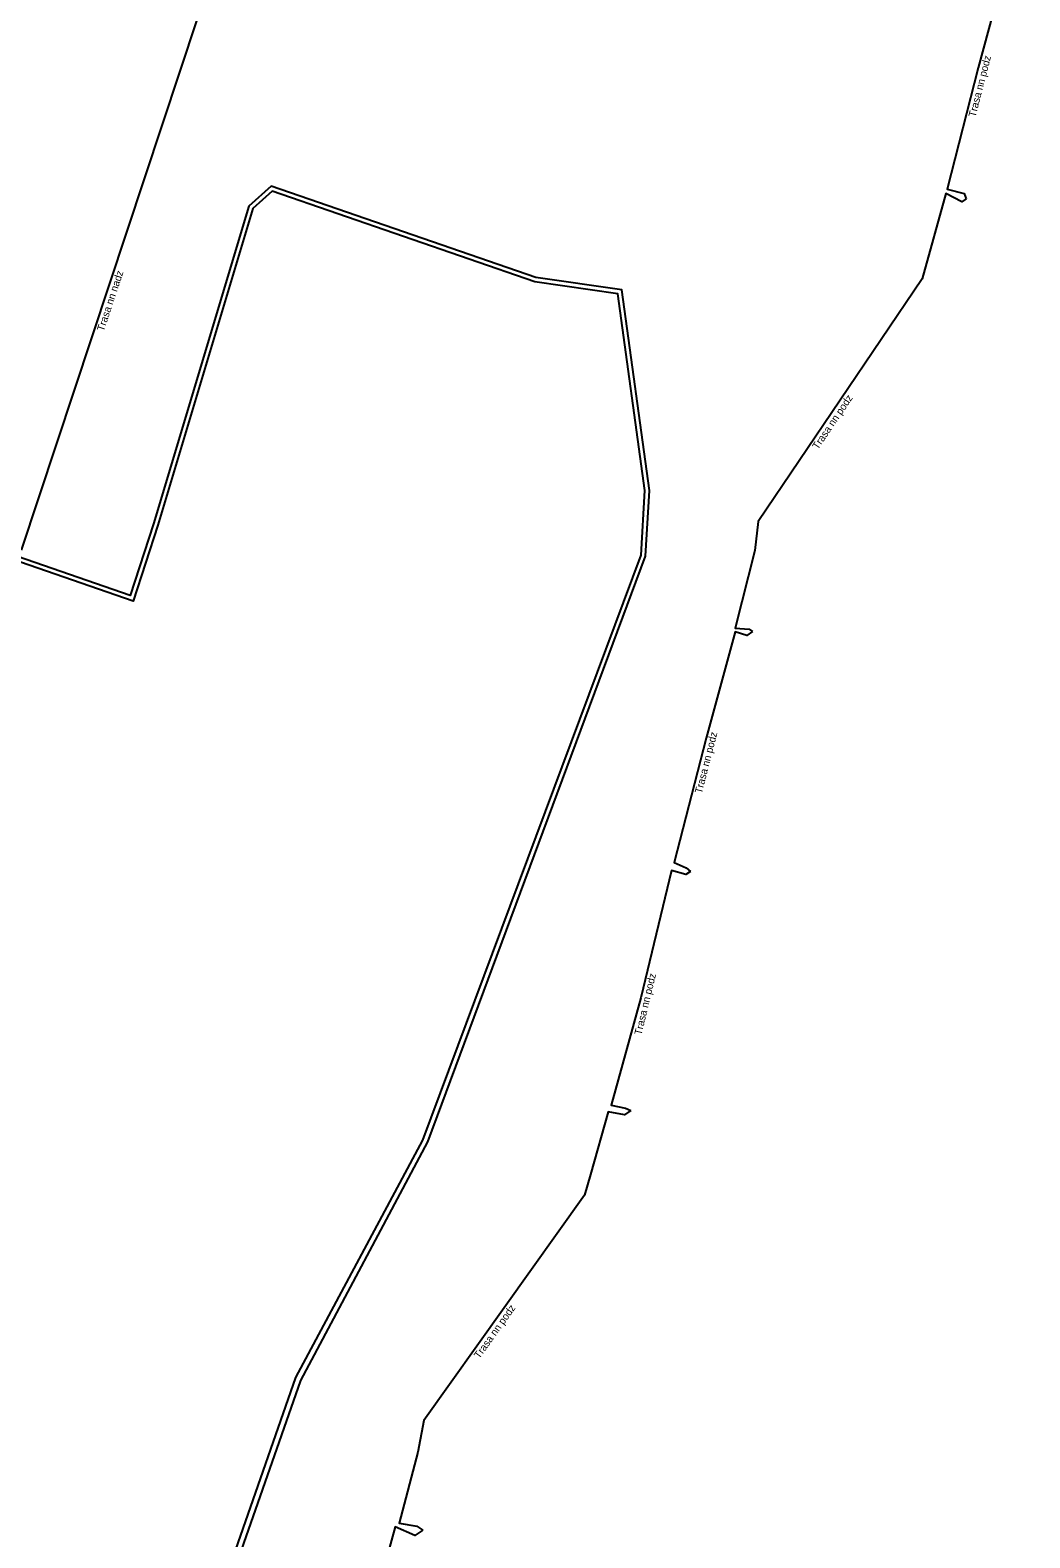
# Model space of a CAD drawing. Extents: x -843786 to -842968, y -1003095 to -1002172.
# Drawn here: x -843451.5 to -843383.8, y -1002899.3 to -1002797.2 of the extents above; entities that cross this region are included whole.
import ezdxf

# ---------------------------------------------------------------- set-up
doc = ezdxf.new("R2010")
doc.units = 0
doc.layers.add('Spojnice NN', color=7, linetype='Continuous')
doc.layers.add('Vrstva 20', color=7, linetype='Continuous')

msp = doc.modelspace()

# ---------------------------------------------------------------- linework, layer by layer
at = {"layer": 'Spojnice NN'}
for points in [[(-843383.77, -1002792.02), (-843384.13, -1002792.1), (-843385.1, -1002791.73), (-843387.26, -1002799.75), (-843389.37, -1002807.96), (-843388.22, -1002808.25), (-843388.08, -1002808.61)], [(-843452.08, -1002832.43), (-843440.16, -1002796.43)], [(-843458.03, -1002952.19), (-843448.76, -1002933.29), (-843433.14, -1002888.67), (-843424.54, -1002872.49), (-843409.8, -1002832.82), (-843409.54, -1002828.37), (-843411.41, -1002814.78), (-843417.24, -1002813.94), (-843435.17, -1002807.76), (-843436.68, -1002809.11), (-843443.13, -1002830.64), (-843444.71, -1002835.49), (-843464.18, -1002828.76)], [(-843458.52, -1002952.33), (-843449.11, -1002933.26), (-843433.49, -1002888.46), (-843424.89, -1002872.39), (-843410.1, -1002832.76), (-843409.84, -1002828.38), (-843411.68, -1002815.05), (-843417.31, -1002814.24), (-843435.1, -1002808.1), (-843436.41, -1002809.28), (-843442.84, -1002830.73), (-843444.52, -1002835.87), (-843464.56, -1002828.95)], [(-843388.08, -1002808.61), (-843388.37, -1002808.83), (-843389.46, -1002808.25), (-843391.06, -1002814.03), (-843402.18, -1002830.47), (-843402.4, -1002832.44), (-843403.72, -1002837.71), (-843402.77, -1002837.78), (-843402.55, -1002837.92)], [(-843402.55, -1002837.92), (-843402.93, -1002838.2), (-843403.74, -1002837.96), (-843405.69, -1002845.16), (-843407.85, -1002853.58), (-843407.04, -1002853.95), (-843406.76, -1002854.19)], [(-843406.76, -1002854.19), (-843407.08, -1002854.4), (-843408.05, -1002854.11), (-843410.13, -1002862.74), (-843412.12, -1002870.02), (-843411.15, -1002870.23), (-843410.79, -1002870.38)], [(-843410.79, -1002870.38), (-843411.22, -1002870.67), (-843412.33, -1002870.46), (-843413.52, -1002874.71), (-843413.93, -1002876.11), (-843424.81, -1002891.37), (-843425.22, -1002893.53), (-843426.48, -1002898.33), (-843425.29, -1002898.54), (-843424.88, -1002898.81)], [(-843424.88, -1002898.81), (-843425.43, -1002899.17), (-843426.76, -1002898.58), (-843428.5, -1002904.91), (-843430.99, -1002913.87), (-843429.33, -1002914.36), (-843429.06, -1002914.56)]]:
    msp.add_lwpolyline(points, dxfattribs=at)

# ---------------------------------------------------------------- texts
at = {"layer": 'Vrstva 20'}
for s, rotation, p in [('Trasa nn podz', 75.6131, (-843387.45, -1002803.12)), ('Trasa nn nadz', 71.679, (-843446.5, -1002817.63)), ('Trasa nn podz', 55.9038, (-843398.13, -1002825.64)), ('Trasa nn podz', 75.6381, (-843405.99, -1002848.94)), ('Trasa nn podz', 76.4716, (-843410.08, -1002865.3)), ('Trasa nn podz', 54.5341, (-843421.06, -1002887.23))]:
    msp.add_text(s, height=0.5, rotation=rotation, dxfattribs=at).set_placement(p)

doc.saveas('drawing.dxf')
